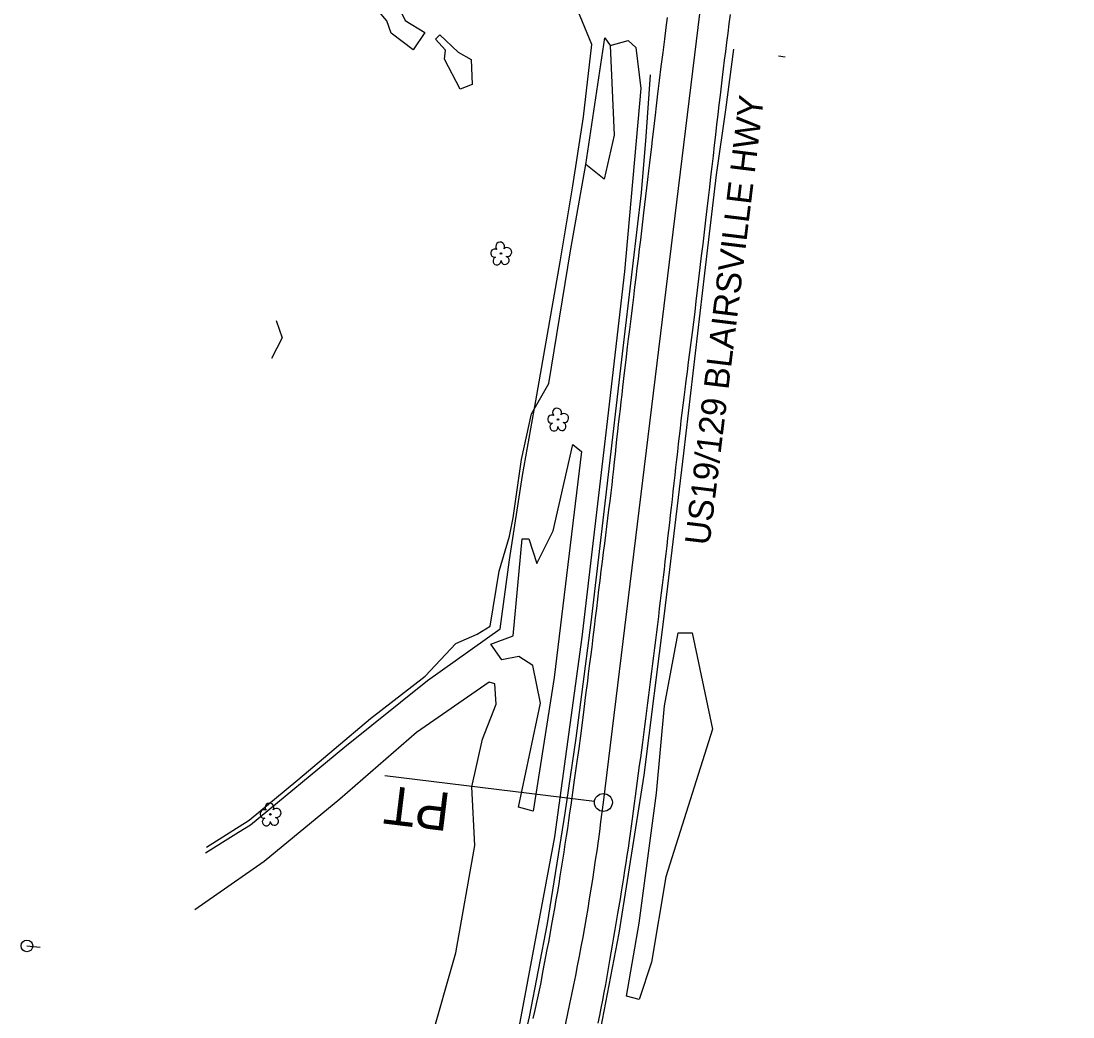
# Model space of a CAD drawing. Extents: x 479429 to 482809, y 488118 to 492379.
# Drawn here: x 480957.4 to 481398, y 489456.1 to 489873.1 of the extents above; entities that cross this region are included whole.
import ezdxf

# ---------------------------------------------------------------- set-up
doc = ezdxf.new("R2010")
doc.units = 0
for name, color, linetype in [('Exist Guardrail', 7, 'Continuous'), ('Exist Horizontal Alignment', 7, 'Continuous'), ('Exist Other Culture Fence Line', 7, 'Continuous'), ('Exist Other Culture Sign', 7, 'Continuous'), ('Exist Roads EOP', 7, 'Continuous'), ('Exist Roads EOP Text', 7, 'Continuous'), ('Exist Utilities Power Pole CELL', 7, 'Continuous'), ('Exist Vegetation Hedge Row', 7, 'Continuous'), ('Exist Vegetation Tree CELL', 7, 'Continuous'), ('Exist Vegetation Woods Line', 7, 'Continuous')]:
    doc.layers.add(name, color=color, linetype=linetype)

msp = doc.modelspace()

# ---------------------------------------------------------------- linework, layer by layer
at = {"layer": 'Exist Guardrail'}
for points in [[(481255.84, 489861.33), (481252.41, 489835.87), (481248.56, 489808.7), (481243.62, 489767.54)], [(481213.58, 489770.37), (481217.32, 489801.15), (481219.26, 489824.69), (481221.03, 489850.54)], [(481127.93, 489321.27), (481143.27, 489358.47), (481160.51, 489413.03), (481170.35, 489456.09), (481177.9, 489495.17), (481185.25, 489541.39), (481189.95, 489572.74), (481196.12, 489621.29), (481202.28, 489673.59), (481209.04, 489731.3), (481213.58, 489770.37)], [(481243.62, 489767.54), (481234.85, 489692.14), (481226.82, 489624.9), (481218.29, 489557.25), (481207.78, 489491.18), (481193.85, 489418.57), (481192.36, 489411.18), (481192.08, 489406.88), (481192.44, 489401.65), (481193.22, 489399.06), (481195.38, 489394.97), (481198.33, 489391.63), (481202.58, 489388.42), (481206.38, 489387.09), (481209.6, 489386.42)]]:
    msp.add_lwpolyline(points, dxfattribs=at)
at = {"layer": 'Exist Horizontal Alignment'}
for p, q in [((481201.31, 489545.89), (481397.95, 491156.7)), ((481197.58, 489546.34), (481109.81, 489557.06))]:
    msp.add_line(p, q, dxfattribs=at)
msp.add_circle((481201.31, 489545.89), 3.75, dxfattribs=at)
msp.add_arc((480215.08, 489666.29), 993.55, 345.52039, 353.03983, dxfattribs=at)
at = {"layer": 'Exist Other Culture Fence Line'}
for points in [[(481183.22, 489772.25), (481188.48, 489804.1), (481193.02, 489832.95), (481196.53, 489863.2), (481191.59, 489875.1), (481177.79, 489907.67), (481173.12, 489924.6), (481162.26, 489970.6), (481160.25, 489984.01), (481158.46, 490003.55), (481157.44, 490018.78), (481158.75, 490046.82), (481160.74, 490066.36), (481162.87, 490080.79)], [(481034.67, 489524.8), (481048.56, 489533.45), (481053.48, 489536.51), (481093.02, 489569.22), (481127.65, 489596.95), (481158.01, 489618.61), (481161.98, 489647.47), (481167.38, 489682.85), (481173.07, 489714.02), (481183.22, 489772.25)]]:
    msp.add_lwpolyline(points, dxfattribs=at)
at = {"layer": 'Exist Other Culture Sign'}
msp.add_line((481277.42, 489857.95), (481274.66, 489858.35), dxfattribs=at)
at = {"layer": 'Exist Roads EOP'}
for points in [[(481171.93, 489455.39), (481172.6, 489458.38), (481173.86, 489464.15), (481175.04, 489469.85), (481176.15, 489475.55), (481177.26, 489481.36), (481177.82, 489484.32), (481178.39, 489487.39), (481179, 489490.67), (481179.63, 489494.15), (481180.3, 489497.84), (481180.96, 489501.55), (481181.58, 489505.13), (481182.17, 489508.56), (481182.72, 489511.85), (481183.25, 489515.09), (481183.78, 489518.37), (481184.31, 489521.68), (481184.84, 489525.03), (481185.36, 489528.39), (481185.87, 489531.72), (481186.37, 489535.03), (481186.85, 489538.3), (481187.32, 489541.55), (481187.79, 489544.76), (481188.24, 489547.94), (481188.69, 489551.09), (481189.13, 489554.18), (481189.55, 489557.19), (481190.37, 489563), (481191.14, 489568.53), (481191.84, 489573.8), (481192.52, 489579.17), (481193.24, 489584.98), (481193.98, 489590.92), (481194.72, 489596.7), (481195.12, 489599.72), (481195.55, 489603.09), (481196.02, 489606.82), (481196.54, 489610.9), (481197.07, 489615.11), (481197.57, 489619.23), (481198.05, 489623.24), (481198.52, 489627.16), (481198.97, 489631.04), (481199.44, 489634.94), (481199.92, 489638.87), (481200.41, 489642.83), (481200.9, 489646.75), (481201.38, 489650.56), (481201.85, 489654.26), (481202.3, 489657.85), (481202.74, 489661.39), (481203.19, 489664.93), (481203.64, 489668.46), (481204.09, 489671.98), (481204.53, 489675.46), (481204.94, 489678.85), (481205.31, 489682.15), (481205.66, 489685.37), (481206, 489688.54), (481206.33, 489691.7), (481206.67, 489694.87), (481207, 489698.03), (481207.34, 489701.19), (481207.69, 489704.33), (481208.05, 489707.46), (481208.41, 489710.58), (481208.77, 489713.68), (481209.13, 489716.75), (481209.48, 489719.79), (481210.15, 489725.73), (481210.79, 489731.25), (481211.44, 489736.62), (481211.85, 489739.97), (481212.33, 489743.87), (481212.89, 489748.33), (481213.47, 489752.96), (481214.01, 489757.4), (481214.53, 489761.64), (481215.03, 489765.69), (481215.5, 489769.63), (481215.98, 489773.56), (481216.45, 489777.49), (481216.92, 489781.41), (481217.39, 489785.27), (481217.84, 489789.04), (481218.28, 489792.7), (481218.71, 489796.26), (481219.13, 489799.77), (481219.54, 489803.28), (481219.96, 489806.79), (481220.37, 489810.31), (481220.77, 489813.77), (481221.16, 489817.13), (481221.54, 489820.37), (481221.91, 489823.52), (481222.29, 489826.71), (481222.69, 489830.11), (481223.11, 489833.72), (481223.56, 489837.54), (481224.01, 489841.34), (481224.43, 489844.88), (481224.83, 489848.16), (481225.56, 489854.1), (481226.3, 489859.87), (481227.04, 489865.5), (481227.65, 489870.32), (481228.17, 489874.59)], [(481254.4, 489875.79), (481253.9, 489871.95), (481253.39, 489868.02), (481252.88, 489864.09), (481252.4, 489860.29), (481251.95, 489856.62), (481251.52, 489853.07), (481251.09, 489849.52), (481250.65, 489845.83), (481250.18, 489841.99), (481249.68, 489838.02), (481249.18, 489833.92), (481248.69, 489829.73), (481248.2, 489825.44), (481247.71, 489821.06), (481247.22, 489816.63), (481246.73, 489812.23), (481246.23, 489807.84), (481245.72, 489803.47), (481245.2, 489799.03), (481244.65, 489794.41), (481244.08, 489789.63), (481243.48, 489784.67), (481242.88, 489779.67), (481242.29, 489774.73), (481241.71, 489769.88), (481241.16, 489765.09), (481240.61, 489760.4), (481240.07, 489755.82), (481239.53, 489751.35), (481239.01, 489747), (481238.48, 489742.73), (481237.94, 489738.5), (481237.4, 489734.32), (481236.85, 489730.19), (481236.32, 489726.19), (481235.82, 489722.41), (481235.37, 489718.85), (481234.95, 489715.5), (481234.56, 489712.25), (481234.17, 489709.01), (481233.79, 489705.75), (481233.41, 489702.49), (481233.04, 489699.23), (481232.67, 489695.98), (481232.3, 489692.72), (481231.93, 489689.47), (481231.56, 489686.2), (481231.19, 489682.88), (481230.81, 489679.53), (481230.43, 489676.13), (481230.04, 489672.74), (481229.67, 489669.42), (481229.3, 489666.15), (481228.94, 489662.95), (481228.58, 489659.77), (481228.22, 489656.56), (481227.85, 489653.31), (481227.47, 489650.04), (481227.08, 489646.75), (481226.69, 489643.47), (481226.3, 489640.19), (481225.9, 489636.92), (481225.5, 489633.64), (481225.1, 489630.36), (481224.71, 489627.06), (481224.33, 489623.76), (481223.94, 489620.46), (481223.55, 489617.16), (481223.15, 489613.88), (481222.74, 489610.6), (481222.33, 489607.32), (481221.92, 489604.04), (481221.5, 489600.75), (481221.08, 489597.45), (481220.66, 489594.15), (481220.23, 489590.86), (481219.81, 489587.56), (481219.39, 489584.27), (481218.96, 489580.97), (481218.53, 489577.67), (481218.09, 489574.37), (481217.66, 489571.06), (481217.22, 489567.77), (481216.78, 489564.52), (481216.35, 489561.3), (481215.92, 489558.11), (481215.5, 489554.94), (481215.07, 489551.76), (481214.64, 489548.58), (481214.21, 489545.39), (481213.79, 489542.22), (481213.36, 489539.09), (481212.93, 489536), (481212.51, 489532.94), (481212.07, 489529.89), (481211.63, 489526.81), (481211.17, 489523.69), (481210.69, 489520.55), (481210.21, 489517.43), (481209.74, 489514.37), (481208.8, 489508.48), (481208.32, 489505.54), (481207.81, 489502.49), (481207.28, 489499.33), (481206.71, 489496.04), (481206.14, 489492.72), (481205.57, 489489.42), (481205.01, 489486.16), (481204.44, 489482.92), (481203.88, 489479.67), (481203.31, 489476.39), (481202.72, 489473.06), (481202.13, 489469.7), (481201.52, 489466.34), (481200.91, 489463.05), (481200.29, 489459.82), (481199.65, 489456.65), (481199.02, 489453.52)]]:
    msp.add_lwpolyline(points, dxfattribs=at)
at = {"layer": 'Exist Utilities Power Pole CELL'}
for q in [(480965.47, 489485.28), (480959.87, 489485.84)]:
    msp.add_line((480959.87, 489485.84), q, dxfattribs=at)
msp.add_circle((480959.87, 489485.84), 2.45, dxfattribs=at)
at = {"layer": 'Exist Vegetation Hedge Row'}
msp.add_line((481187.58, 489776.84), (481193.95, 489813.03), dxfattribs=at)
for points in [[(481112.7, 489885.08), (481118.35, 489873.35), (481126.56, 489868.21), (481121.64, 489861.04), (481112.44, 489868.05), (481110.55, 489873.12), (481105.06, 489879.75), (481105.8, 489883.33), (481112.7, 489885.08)], [(481141.29, 489844.57), (481134.82, 489857.07), (481135.17, 489860.88), (481131.02, 489865.53), (481132.77, 489867.27), (481140.54, 489860.03), (481145.96, 489856.95), (481146.41, 489846.52), (481141.29, 489844.57)], [(481204.13, 489862.88), (481211.62, 489864.93), (481214.85, 489861.99), (481216.99, 489844.77), (481210.19, 489768.18)], [(481035.11, 489527.16), (481052.96, 489538.42), (481073.3, 489555.37), (481103.84, 489580.99), (481126.69, 489598.8), (481139.52, 489612.38), (481148.45, 489616.33), (481153.88, 489619.75), (481157.6, 489642.76), (481161.98, 489657.36), (481163.48, 489665.11), (481166.95, 489689.54), (481171.18, 489708.64), (481178.4, 489721.28), (481187.58, 489776.84)], [(481210.19, 489768.18), (481202.55, 489702.96), (481192.31, 489615.09), (481180.88, 489531.49), (481165.89, 489451.67)], [(481064.23, 489747.67), (481066.72, 489740.42), (481062.3, 489731.84)], [(481128.79, 489445.23), (481139.49, 489482.89), (481147.5, 489527.82), (481146.27, 489552.37), (481150.68, 489572.42), (481156.36, 489587.06), (481155.78, 489595.53), (481153.53, 489596.23), (481123.01, 489575.17), (481090.95, 489547.33), (481059.27, 489521.18), (481030.18, 489500.86)]]:
    msp.add_lwpolyline(points, dxfattribs=at)
at = {"layer": 'Exist Vegetation Tree CELL'}
for p, q in [((481158.46, 489775.75), (481158.46, 489775.75)), ((481182.3, 489706.22), (481182.3, 489706.22)), ((481061.85, 489540.91), (481061.85, 489540.91))]:
    msp.add_line(p, q, dxfattribs=at)
for centre in [(481158.46, 489775.75), (481182.3, 489706.22), (481061.85, 489540.91)]:
    msp.add_circle(centre, 0.326, dxfattribs=at)
for centre, radius, start, end in [((481158.08, 489778.63), 1.86, 330.1651, 219.7134), ((481155.86, 489775.91), 1.73, 62.6636, 279.3457), ((481161.01, 489776.34), 1.9, 257.1011, 134.1999), ((481156.76, 489772.63), 1.69, 111.5671, 6.231), ((481160.13, 489772.86), 1.7, 181.2822, 74.56), ((481181.92, 489709.09), 1.86, 330.1651, 219.7134), ((481179.7, 489706.37), 1.73, 62.6636, 279.3457), ((481183.97, 489703.32), 1.7, 181.2822, 74.56), ((481184.85, 489706.81), 1.9, 257.1011, 134.1999), ((481180.6, 489703.1), 1.69, 111.5671, 6.231), ((481059.24, 489541.06), 1.73, 62.6636, 279.3457), ((481061.46, 489543.78), 1.86, 330.1651, 219.7134), ((481064.4, 489541.5), 1.9, 257.1011, 134.1999), ((481060.15, 489537.79), 1.69, 111.5671, 6.231), ((481063.52, 489538.01), 1.7, 181.2822, 74.56)]:
    msp.add_arc(centre, radius, start, end, dxfattribs=at)
at = {"layer": 'Exist Vegetation Woods Line'}
for points in [[(481193.95, 489813.03), (481201.96, 489866.01), (481204.13, 489862.88)], [(481204.13, 489862.88), (481205.79, 489825.33), (481201.67, 489806.89)], [(481201.67, 489806.89), (481193.95, 489813.03)], [(481163.59, 489615.63), (481167.32, 489656.32), (481170.11, 489656.27), (481173.47, 489645.97), (481180.28, 489659.63), (481188.46, 489695.75), (481192.17, 489692.86), (481180.73, 489598.2), (481171.84, 489542.31), (481165.8, 489543.95), (481174.92, 489587.52), (481171.79, 489603.27), (481165.87, 489607), (481158.72, 489605.67), (481154.13, 489612.11)], [(481238.44, 489616.85), (481247.02, 489576.52), (481227.47, 489514.68), (481221.47, 489479.05), (481216.24, 489463.34), (481211.05, 489464.74), (481216.33, 489495.31), (481223.6, 489549.84), (481226.96, 489586.38), (481232.57, 489616.94), (481238.44, 489616.85)], [(481154.13, 489612.11), (481163.59, 489615.63)]]:
    msp.add_lwpolyline(points, dxfattribs=at)

# ---------------------------------------------------------------- texts
at = {"layer": 'Exist Horizontal Alignment'}
msp.add_text('PT', height=16, rotation=173.0398, dxfattribs=at).set_placement((481137.82, 489549.71))
at = {"layer": 'Exist Roads EOP Text'}
msp.add_text('US19/129 BLAIRSVILLE HWY', height=10.4, rotation=83.0603, dxfattribs=at).set_placement((481245.69, 489653.23))

doc.saveas('drawing.dxf')
